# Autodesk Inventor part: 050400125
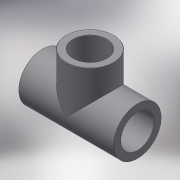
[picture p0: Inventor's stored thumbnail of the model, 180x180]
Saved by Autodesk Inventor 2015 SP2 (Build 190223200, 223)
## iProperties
Created: 2017-10
Part Number: 050400125
Material: Generic
Description: PLASSON TEE-CEMENT PVC 125
Document SubType Name: Modeling
Designer: KIM
Density: 1 g/cm^3
Appearance: Default
Author: KIM
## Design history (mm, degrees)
derived "050400.ipt"
feature "Solid1::050400.ipt"
feature "Solid2::050400.ipt"
tag "TaggingFeature1"
body "Solid1"
other parameters: "d1" = 148, "d2" = 69, "d4" = 125, "d5" = 112.5, "d7" = 1.25, "d8" = 69, "d9" = 135, "d10" = 148, "d11" = 125, "d12" = 112.5, "d15" = 0, "d17" = 0, "d18" = 125, "d19" = 112.5, "d20" = 125, "d21" = 69, "d22" = 0, "d23" = 69, "d24" = 1.25, "d_" = 125, "E_" = 148, "l_" = 69, "Z_" = 66
